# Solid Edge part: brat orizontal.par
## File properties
Author: User
Template: iso metric part.par
Last saved by: User
Revision: 1
Application: Solid Edge
Accuracy: 0.990
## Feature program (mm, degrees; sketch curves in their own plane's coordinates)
sketch for "unnamed Protrusion 1" plane through (0, 0, 0) normal (0, 0, 1) x-axis (1, 0, 0)
  line (-75, -6) -> (75, -6)
  line (75, -6) -> (75, 6)
  line (75, 6) -> (-75, 6)
  line (-75, 6) -> (-75, -6)
  dimension (linear) = 75
  dimension (linear) = 75
extrude "unnamed Protrusion 1" add finite 6 along +normal
sketch for "ExtrudedCutout_1" plane through (0, 0, 6) normal (0, 0, 1) x-axis (1, 0, 0)
  circle centre (67.5058, 0) radius 3.5
extrude "ExtrudedCutout_1" cut finite 12 along -normal
mirror "unnamed Mirror 1" of "ExtrudedCutout_1" about plane through (0, 0, 0) normal (1, 0, 0)
extrude "unnamed Cutout 1" cut finite 12
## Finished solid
Body 1: solid body, 8 faces, 16 edges, 8 vertices.
  Faces by surface: plane 6, cylinder 2
  Edges by curve: line 12, circle 4
Bounding box of the edges (mm): 150.000 x 12.000 x 6.000, from (-75, -6, 0) to (75, 6, 6).
Cylindrical faces by radius (mm): R3.5 x2
Planar faces by outward normal: +x 1, +y 1, +z 1, -x 1, -y 1, -z 1
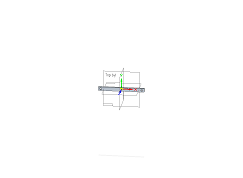
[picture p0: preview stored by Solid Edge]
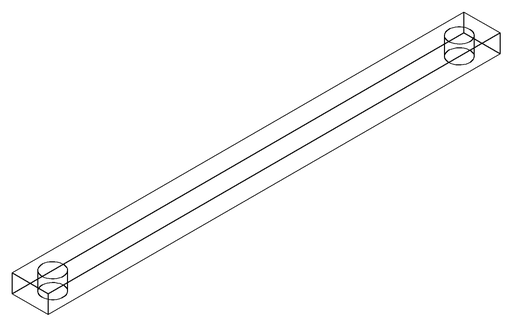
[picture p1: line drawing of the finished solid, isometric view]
